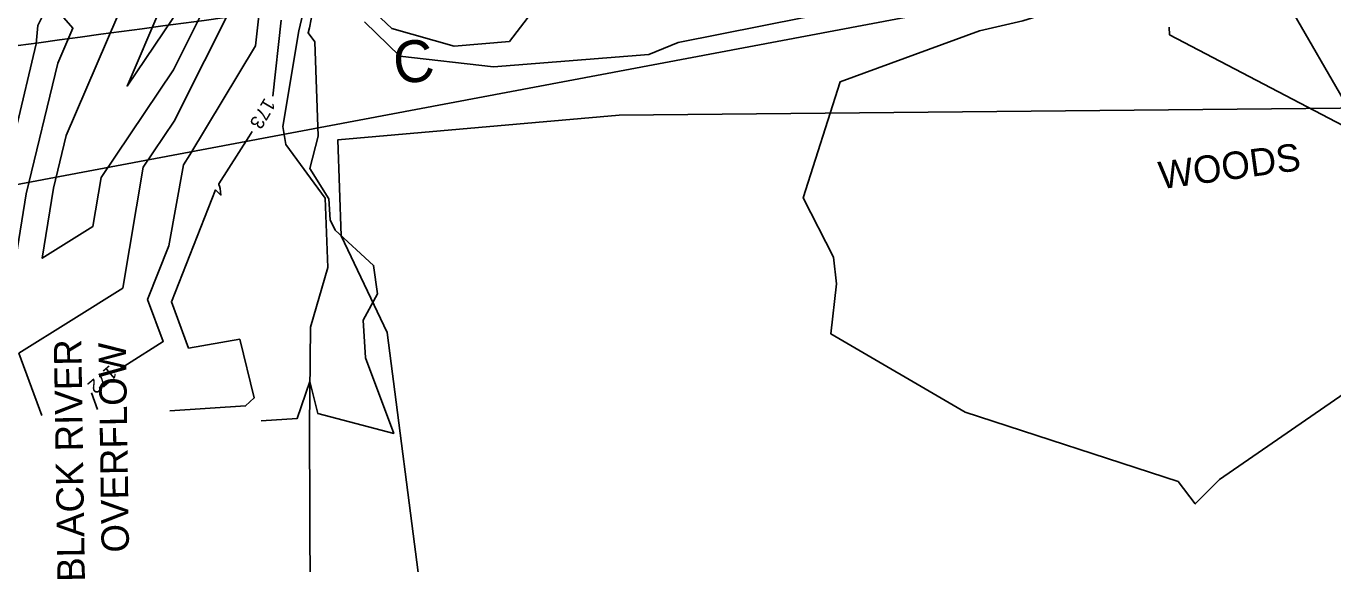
# Model space of a CAD drawing. Extents: x 2086416 to 2115205, y 575507 to 632762.
# Drawn here: x 2112066 to 2112256.5, y 581619.1 to 581697.5 of the extents above; entities that cross this region are included whole.
import ezdxf

# ---------------------------------------------------------------- set-up
doc = ezdxf.new("R2010")
doc.units = 0
for name, color, linetype in [('DTM Contours Major', 7, 'Continuous'), ('DTM Contours Minor', 7, 'Continuous'), ('DTM Contours Minor Text', 7, 'Continuous'), ('Exist Hydro Stream or Body of Water', 7, 'Continuous'), ('Exist Hydro Stream or Body of Water Text', 7, 'Continuous'), ('Exist Hydrographic FEMA Cross Section', 7, 'Continuous'), ('Exist Right of Way Line', 7, 'Continuous'), ('Exist Vegetation Woods Line', 7, 'Continuous'), ('Exist Vegetation Woods Line Text', 7, 'Continuous'), ('Prop SS Cut Line', 7, 'Continuous'), ('Prop SS Cut Text', 7, 'Continuous'), ('Prop SS Fill Line', 7, 'Continuous')]:
    doc.layers.add(name, color=color, linetype=linetype)

msp = doc.modelspace()

# ---------------------------------------------------------------- linework, layer by layer
at = {"layer": 'DTM Contours Major'}
for points in [[(2112068.37, 581712.85), (2112069.61, 581710.85), (2112070.24, 581708.91), (2112079.26, 581698.72), (2112071.88, 581681.59), (2112070.02, 581673.88), (2112068.38, 581663.67), (2112075.73, 581668.3), (2112076.94, 581675.45), (2112087.51, 581691.15), (2112092.08, 581700.28)], [(2112115.35, 581698.13), (2112120.53, 581693.14), (2112134.17, 581691.59), (2112156.79, 581693.38), (2112161.11, 581695.13), (2112179.46, 581698.78), (2112193.13, 581703.79), (2112205.82, 581706.66), (2112209.41, 581707.04), (2112211.23, 581707.28)]]:
    msp.add_lwpolyline(points, dxfattribs=at)
at = {"layer": 'DTM Contours Minor'}
for points in [[(2112075.94, 581709.66), (2112082.98, 581703.27), (2112085.68, 581700.21), (2112080.75, 581688.78), (2112087.39, 581698.64), (2112088.48, 581700.81), (2112089.15, 581701.86), (2112092.6, 581709.12), (2112094.04, 581714.82), (2112096.43, 581727.47), (2112096.46, 581728.31), (2112096.36, 581728.84), (2112090.96, 581740.97), (2112090.84, 581746.67)], [(2112343.34, 581704.65), (2112350.12, 581713.38), (2112332.97, 581725.6), (2112308.89, 581715.82), (2112296.37, 581715.24), (2112275.63, 581707.81), (2112279.07, 581713.44), (2112269.95, 581714.02), (2112259.58, 581711.35), (2112249.1, 581710.06), (2112244.24, 581707.7), (2112247.67, 581704.8), (2112261.26, 581681.31), (2112232.74, 581696.26), (2112232.68, 581697.35)], [(2112099.58, 581721.47), (2112099.78, 581716.48), (2112098.96, 581715.12), (2112098.92, 581714.21), (2112096.91, 581702.43), (2112096.94, 581702.35), (2112096.95, 581702.25), (2112096.93, 581702.06), (2112096.43, 581701.23), (2112087.62, 581683.65), (2112083.11, 581676.95), (2112080.12, 581659.33), (2112072.6, 581654.59), (2112064.96, 581649.82), (2112068.33, 581640.74)], [(2112061.21, 581719.46), (2112062.6, 581717.03), (2112064.76, 581713.69), (2112066.89, 581710.24), (2112070.14, 581700.28), (2112072.84, 581697.24), (2112070.63, 581692.11), (2112066.05, 581673.08), (2112062.82, 581653.08), (2112059.86, 581649.8), (2112053.49, 581643.44), (2112049.37, 581635.99)], [(2112064.52, 581708.58), (2112068.43, 581698.96), (2112067.72, 581697.62), (2112067.49, 581694.94), (2112064.51, 581682.38)], [(2112232.33, 581703.34), (2112232.24, 581704.8), (2112211.35, 581698.28), (2112205.02, 581696.84), (2112184.7, 581689.39), (2112179.33, 581672.48), (2112183.71, 581663.85), (2112184.18, 581659.93), (2112183.36, 581652.63), (2112202.94, 581641.22), (2112233.96, 581631.14), (2112236.48, 581627.86), (2112240, 581631.41), (2112272.92, 581654.12), (2112271.45, 581659.3)], [(2112108.33, 581702.36), (2112107.36, 581697.28), (2112107.13, 581696.55), (2112108.13, 581695.25), (2112108.59, 581681.48), (2112107.39, 581676.76), (2112110.15, 581672.34), (2112110.35, 581669.26), (2112111.1, 581667.76), (2112116.69, 581662.63), (2112117.27, 581658.48), (2112115.14, 581654.66), (2112115.51, 581649.15), (2112119.63, 581638.14), (2112108.56, 581641.02), (2112107.39, 581645.69), (2112105.53, 581640.29), (2112100.31, 581639.95)], [(2112100.09, 581700.33), (2112099.46, 581694.62), (2112089.9, 581678.74), (2112088.97, 581677.27), (2112086.82, 581665.48), (2112083.74, 581657.67), (2112086.01, 581651.53), (2112080.79, 581648.23), (2112079.67, 581647.54)], [(2112103.23, 581698.4), (2112102.01, 581687.29)], [(2112098.96, 581682.14), (2112098.5, 581681.37), (2112094.12, 581674.51), (2112094.14, 581674.42), (2112094.21, 581674.17), (2112094.3, 581673.86), (2112094.43, 581672.89), (2112093.64, 581673.63), (2112087.21, 581657.34), (2112089.71, 581650.57), (2112097.16, 581651.86), (2112099.27, 581643.3), (2112098.03, 581642.14), (2112086.97, 581641.41)], [(2112075.54, 581644.03), (2112076.44, 581641.61)]]:
    msp.add_lwpolyline(points, dxfattribs=at)
at = {"layer": 'Exist Hydro Stream or Body of Water'}
msp.add_line((2112107.33, 581639.18), (2112107.47, 581653.64), dxfattribs=at)
for points in [[(2112107.47, 581653.64), (2112110.03, 581662.34), (2112109.6, 581672.44), (2112103.87, 581680.24), (2112103.47, 581682.89), (2112105.77, 581696.84), (2112107.09, 581702.48), (2112104.98, 581704.54), (2112102.35, 581710.99), (2112103.02, 581715.3)], [(2112107.33, 581639.18), (2112107.41, 581614.06)]]:
    msp.add_lwpolyline(points, dxfattribs=at)
at = {"layer": 'Exist Hydrographic FEMA Cross Section'}
msp.add_lwpolyline([(2112356.49, 581719.74), (2112346.58, 581718.49), (2112341.62, 581717.86), (2112336.66, 581717.24), (2112326.74, 581715.99), (2112316.82, 581714.73), (2112306.91, 581713.48), (2112296.99, 581712.23), (2112287.07, 581710.98), (2112277.16, 581709.73), (2112267.24, 581708.48), (2112257.32, 581707.22), (2112247.41, 581705.97), (2112237.49, 581704.72), (2112227.57, 581703.47), (2112217.66, 581702.22), (2112207.74, 581700.97), (2112201.88, 581700.22), (2111922.67, 581647.71)], dxfattribs=at)
at = {"layer": 'Exist Right of Way Line'}
msp.add_arc((2100483.79, 667614.96), 86697.25, 277.6423877, 277.7710056, dxfattribs=at)
at = {"layer": 'Exist Vegetation Woods Line'}
for points in [[(2112111.96, 581666.92), (2112111.49, 581680.94), (2112152.5, 581684.53), (2112262.63, 581685.59), (2112360.38, 581709.42), (2112461.66, 581723.72), (2112531.13, 581752.37)], [(2112223.29, 581547.33), (2112206.03, 581551.03), (2112187.8, 581558.85), (2112171.15, 581560.85), (2112157.41, 581561.71), (2112138.87, 581534.84), (2112134.62, 581530.07), (2112130.01, 581530.64), (2112130.9, 581571.76), (2112123.57, 581614.86), (2112118.67, 581652.85), (2112111.96, 581666.92)]]:
    msp.add_lwpolyline(points, dxfattribs=at)
at = {"layer": 'Prop SS Cut Line'}
msp.add_line((2112111.36, 581704.72), (2112119.34, 581697.16), dxfattribs=at)
msp.add_lwpolyline([(2112119.34, 581697.16), (2112128.42, 581694.6), (2112136.48, 581695.27)], dxfattribs=at)
at = {"layer": 'Prop SS Fill Line'}
msp.add_lwpolyline([(2112146.19, 581706.78), (2112140.89, 581699.91), (2112139.69, 581699.44), (2112136.48, 581695.27)], dxfattribs=at)

# ---------------------------------------------------------------- texts
at = {"layer": 'DTM Contours Minor Text'}
for s, rotation, p in [('173', 239.3647, (2112100.81, 581687.17)), ('172', 220.3491, (2112078.21, 581648.18))]:
    msp.add_text(s, height=2, rotation=rotation, dxfattribs=at).set_placement(p)
at = {"layer": 'Exist Hydro Stream or Body of Water Text'}
for s, p in [('BLACK RIVER', (2112074.6, 581616.52)), ('OVERFLOW', (2112081.03, 581620.79))]:
    msp.add_text(s, height=4, rotation=90.8753, dxfattribs=at).set_placement(p)
at = {"layer": 'Exist Vegetation Woods Line Text'}
msp.add_text('WOODS', height=4, rotation=7.771, dxfattribs=at).set_placement((2112231.43, 581673.73))
at = {"layer": 'Prop SS Cut Text'}
msp.add_text('C', height=6.1, rotation=7.771, dxfattribs=at).set_placement((2112119.98, 581688.96))

doc.saveas('drawing.dxf')
